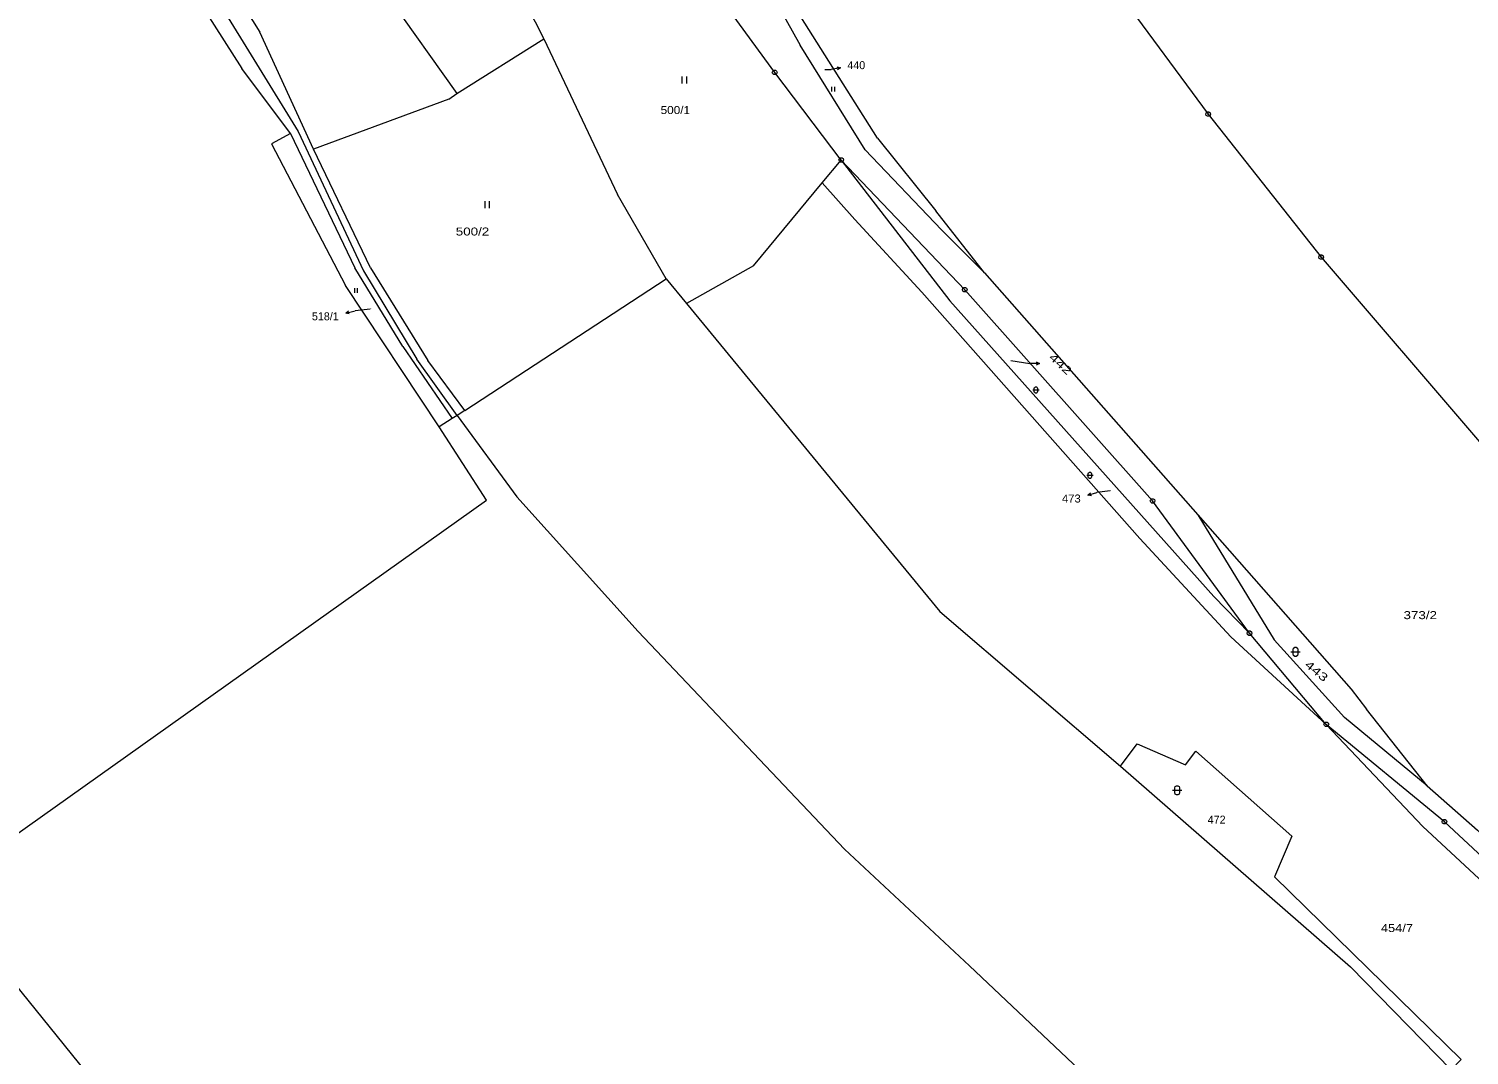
# Model space of a CAD drawing. Extents: x -687390 to -684106, y -954833 to -951648.
# Drawn here: x -686675.9 to -686369.8, y -953282.2 to -953064 of the extents above; entities that cross this region are included whole.
import ezdxf
from ezdxf.enums import TextEntityAlignment as Align

# ---------------------------------------------------------------- set-up
doc = ezdxf.new("R2010")
doc.units = 0
doc.header["$LTSCALE"] = 0.68
for name, color, linetype, lineweight in [('1', 7, 'Continuous', 13), ('3', 7, 'Continuous', 13), ('7', 7, 'Continuous', 13), ('8', 7, 'Continuous', 13)]:
    doc.layers.add(name, color=color, linetype=linetype, lineweight=lineweight)
doc.layers.add('2', color=7, linetype='Continuous')

msp = doc.modelspace()

# ---------------------------------------------------------------- linework, layer by layer
at = {"layer": '1'}
for p, q in [((-686650.19, -952985.77), (-686584.91, -953077.81)), ((-686655.57, -953033.26), (-686630.63, -953072.46)), ((-686495.55, -953087.28), (-686514, -953058.06)), ((-686516.33, -953059.65), (-686511.96, -953067.55)), ((-686615.36, -953089.59), (-686626.76, -953064.78)), ((-686566.44, -953066.15), (-686550.8, -953099.29)), ((-686498.13, -953089.75), (-686511.96, -953067.55)), ((-686620.25, -953086.28), (-686630.63, -953072.46)), ((-686586.61, -953078.97), (-686615.36, -953089.59)), ((-686620.25, -953086.28), (-686624.28, -953088.48)), ((-686620.25, -953086.28), (-686606.61, -953114.85)), ((-686624.28, -953088.48), (-686608.59, -953118.58)), ((-686603.25, -953114.87), (-686615.36, -953089.59)), ((-686495.55, -953087.28), (-686483.12, -953102.71)), ((-686503.23, -953091.93), (-686480.19, -953121.89)), ((-686498.13, -953089.75), (-686481.92, -953106.74)), ((-686507.28, -953096.81), (-686500.39, -953104.56)), ((-686486.09, -953119.99), (-686500.39, -953104.56)), ((-686472.77, -953115.91), (-686483.12, -953102.71)), ((-686472.77, -953115.91), (-686481.92, -953106.74)), ((-686596.4, -953131.6), (-686606.61, -953114.85)), ((-686603.25, -953114.87), (-686591.1, -953134.51)), ((-686521.9, -953114.4), (-686536.12, -953122.46)), ((-686588.71, -953148.66), (-686608.59, -953118.58)), ((-686486.09, -953119.99), (-686439.79, -953172.41)), ((-686480.19, -953121.89), (-686424.04, -953184.68)), ((-686596.4, -953131.6), (-686585.9, -953146.87)), ((-686584.89, -953146.23), (-686593.43, -953134.24)), ((-686583.23, -953145.16), (-686591.1, -953134.51)), ((-686585.9, -953146.87), (-686588.71, -953148.66)), ((-686584.89, -953146.23), (-686572.2, -953163.52)), ((-686578.63, -953164.25), (-686588.71, -953148.66)), ((-686691.08, -953244.15), (-686578.63, -953164.25)), ((-686572.2, -953163.52), (-686546.41, -953192.14)), ((-686427.48, -953167.34), (-686394.86, -953204.41)), ((-686416.48, -953192.52), (-686424.04, -953184.68)), ((-686502.58, -953238.38), (-686546.41, -953192.14)), ((-686394.86, -953204.41), (-686391.66, -953208.66)), ((-686378.72, -953224.93), (-686391.66, -953208.66)), ((-686400.17, -953211.88), (-686379.66, -953233.62)), ((-686378.72, -953224.93), (-686396.31, -953210.42)), ((-686443.88, -953220.8), (-686395.02, -953263.43)), ((-686502.58, -953238.38), (-686476, -953263.2)), ((-686476, -953263.2), (-686435.25, -953301.66))]:
    msp.add_line(p, q, dxfattribs=at)
for points in [[(-686744.67, -952933.19), (-686724.45, -952954.91), (-686675.78, -953000.89), (-686652.38, -953031), (-686618.65, -953085.9), (-686604.76, -953115.49), (-686593.43, -953134.24)], [(-686498.08, -952961.98), (-686495.25, -952967.14), (-686459.74, -953032.55), (-686443.92, -953056.89), (-686425.27, -953082.18), (-686401.26, -953112.58), (-686367.6, -953151.83), (-686353.01, -953164.57)], [(-686566.44, -953066.15), (-686567.94, -953063.1), (-686613.86, -952983.34)], [(-686670.54, -953001.44), (-686649.45, -953028.64), (-686626.76, -953064.78)], [(-686252.58, -953389.33), (-686292.75, -953324.92), (-686302.57, -953310.07), (-686336.76, -953268.21), (-686375.07, -953232.58), (-686400.17, -953211.88), (-686416.48, -953192.52), (-686437.08, -953164.4), (-686477, -953119.5), (-686503.23, -953091.93), (-686517.39, -953073.32), (-686528.9, -953057.45), (-686535.29, -953045.19), (-686542.46, -953027.04)], [(-686586.61, -953078.97), (-686584.91, -953077.81), (-686566.44, -953066.15)], [(-686521.9, -953114.4), (-686507.28, -953096.81), (-686503.23, -953091.93)], [(-686583.23, -953145.16), (-686540.44, -953117.21), (-686550.8, -953099.29)], [(-686540.44, -953117.21), (-686536.12, -953122.46), (-686482.27, -953187.88)], [(-686472.77, -953115.91), (-686427.48, -953167.34), (-686411.27, -953193.95), (-686396.31, -953210.42)], [(-686583.23, -953145.16), (-686584.89, -953146.23), (-686585.9, -953146.87)], [(-686400.17, -953211.88), (-686420.48, -953193.25), (-686439.79, -953172.41)], [(-686482.27, -953187.88), (-686443.88, -953220.8), (-686440.36, -953216.04), (-686430.06, -953220.52), (-686427.89, -953217.57), (-686407.47, -953235.64), (-686411.17, -953244.26), (-686371.51, -953283.1), (-686373.62, -953285.31), (-686395.02, -953263.43)], [(-686378.72, -953224.93), (-686368.07, -953234.36), (-686335.41, -953264.98), (-686302.65, -953304.78), (-686292.4, -953318.9)], [(-686379.66, -953233.62), (-686346.95, -953264.02), (-686326.9, -953287)], [(-686694.31, -953248.02), (-686654.73, -953296.99), (-686579.98, -953373.97), (-686534.21, -953420.02), (-686500.91, -953457.57), (-686468.1, -953494.74)]]:
    msp.add_lwpolyline(points, dxfattribs=at)
at = {"layer": '3'}
for p, q in [((-686537.09, -953074.15), (-686537.09, -953075.65)), ((-686536.09, -953075.65), (-686536.09, -953074.15)), ((-686505.285, -953076.395), (-686505.285, -953077.4)), ((-686504.615, -953077.4), (-686504.615, -953076.395)), ((-686579.01, -953100.68), (-686579.01, -953102.18)), ((-686578.01, -953102.18), (-686578.01, -953100.68)), ((-686606.675, -953119.145), (-686606.675, -953120.15)), ((-686606.005, -953120.15), (-686606.005, -953119.145))]:
    msp.add_line(p, q, dxfattribs=at)
for points in [[(-686462.56, -953140.81), (-686461.709, -953140.81), (-686461.22, -953140.81)], [(-686451.08, -953158.95), (-686450.229, -953158.95), (-686449.74, -953158.95)], [(-686407.71, -953196.47), (-686406.44, -953196.47), (-686405.71, -953196.47)], [(-686432.87, -953225.9), (-686431.6, -953225.9), (-686430.87, -953225.9)]]:
    msp.add_lwpolyline(points, dxfattribs=at)
for points in [[(-686462.225, -953140.475), (-686462.158, -953140.281), (-686461.99, -953140.16), (-686461.783, -953140.16), (-686461.615, -953140.281), (-686461.548, -953140.475), (-686461.548, -953141.145), (-686461.615, -953141.339), (-686461.783, -953141.46), (-686461.99, -953141.46), (-686462.158, -953141.339), (-686462.225, -953141.145)], [(-686450.745, -953158.615), (-686450.678, -953158.421), (-686450.51, -953158.3), (-686450.303, -953158.3), (-686450.135, -953158.421), (-686450.068, -953158.615), (-686450.068, -953159.285), (-686450.135, -953159.479), (-686450.303, -953159.6), (-686450.51, -953159.6), (-686450.678, -953159.479), (-686450.745, -953159.285)], [(-686407.21, -953195.97), (-686407.11, -953195.68), (-686406.86, -953195.5), (-686406.55, -953195.5), (-686406.3, -953195.68), (-686406.2, -953195.97), (-686406.2, -953196.97), (-686406.3, -953197.26), (-686406.55, -953197.44), (-686406.86, -953197.44), (-686407.11, -953197.26), (-686407.21, -953196.97)], [(-686432.37, -953225.4), (-686432.27, -953225.11), (-686432.02, -953224.93), (-686431.71, -953224.93), (-686431.46, -953225.11), (-686431.36, -953225.4), (-686431.36, -953226.4), (-686431.46, -953226.69), (-686431.71, -953226.87), (-686432.02, -953226.87), (-686432.27, -953226.69), (-686432.37, -953226.4)]]:
    msp.add_lwpolyline(points, close=True, dxfattribs=at)
at = {"layer": '7'}
for p, q in [((-686506.76, -953072.68), (-686505.42, -953072.66)), ((-686503.435, -953072.345), (-686505.42, -953072.66)), ((-686608.51, -953124.476), (-686606.56, -953123.99)), ((-686603.34, -953123.66), (-686606.56, -953123.99)), ((-686467.19, -953134.56), (-686463.16, -953135.17)), ((-686461.15, -953135.191), (-686463.16, -953135.17)), ((-686450.834, -953163.178), (-686448.9, -953162.63)), ((-686446.09, -953162.25), (-686448.9, -953162.63))]:
    msp.add_line(p, q, dxfattribs=at)
for points in [[(-686504.149, -953072.119), (-686503.435, -953072.345), (-686504.044, -953072.781)], [(-686607.779, -953124.639), (-686608.51, -953124.476), (-686607.941, -953123.989)], [(-686461.817, -953134.849), (-686461.15, -953135.191), (-686461.824, -953135.519)], [(-686450.098, -953163.318), (-686450.834, -953163.178), (-686450.281, -953162.673)]]:
    msp.add_lwpolyline(points, dxfattribs=at)
at = {"layer": '8'}
for p, q in [((-686517.51, -953073.32), (-686517.27, -953073.32)), ((-686425.39, -953082.18), (-686425.15, -953082.18)), ((-686503.35, -953091.93), (-686503.11, -953091.93)), ((-686401.38, -953112.58), (-686401.14, -953112.58)), ((-686477.12, -953119.5), (-686476.88, -953119.5)), ((-686437.2, -953164.4), (-686436.96, -953164.4)), ((-686416.6, -953192.52), (-686416.36, -953192.52)), ((-686400.29, -953211.88), (-686400.05, -953211.88)), ((-686375.19, -953232.58), (-686374.95, -953232.58))]:
    msp.add_line(p, q, dxfattribs=at)
for points in [[(-686517.24, -953072.84), (-686516.99, -953073.02), (-686516.89, -953073.31), (-686516.99, -953073.6), (-686517.24, -953073.78), (-686517.55, -953073.78), (-686517.8, -953073.6), (-686517.9, -953073.31), (-686517.8, -953073.02), (-686517.55, -953072.84)], [(-686425.12, -953081.7), (-686424.87, -953081.88), (-686424.77, -953082.17), (-686424.87, -953082.46), (-686425.12, -953082.64), (-686425.43, -953082.64), (-686425.68, -953082.46), (-686425.78, -953082.17), (-686425.68, -953081.88), (-686425.43, -953081.7)], [(-686503.08, -953091.45), (-686502.83, -953091.63), (-686502.73, -953091.92), (-686502.83, -953092.21), (-686503.08, -953092.39), (-686503.39, -953092.39), (-686503.64, -953092.21), (-686503.74, -953091.92), (-686503.64, -953091.63), (-686503.39, -953091.45)], [(-686401.11, -953112.1), (-686400.86, -953112.28), (-686400.76, -953112.57), (-686400.86, -953112.86), (-686401.11, -953113.04), (-686401.42, -953113.04), (-686401.67, -953112.86), (-686401.77, -953112.57), (-686401.67, -953112.28), (-686401.42, -953112.1)], [(-686476.85, -953119.02), (-686476.6, -953119.2), (-686476.5, -953119.49), (-686476.6, -953119.78), (-686476.85, -953119.96), (-686477.16, -953119.96), (-686477.41, -953119.78), (-686477.51, -953119.49), (-686477.41, -953119.2), (-686477.16, -953119.02)], [(-686436.93, -953163.92), (-686436.68, -953164.1), (-686436.58, -953164.39), (-686436.68, -953164.68), (-686436.93, -953164.86), (-686437.24, -953164.86), (-686437.49, -953164.68), (-686437.59, -953164.39), (-686437.49, -953164.1), (-686437.24, -953163.92)], [(-686416.33, -953192.04), (-686416.08, -953192.22), (-686415.98, -953192.51), (-686416.08, -953192.8), (-686416.33, -953192.98), (-686416.64, -953192.98), (-686416.89, -953192.8), (-686416.99, -953192.51), (-686416.89, -953192.22), (-686416.64, -953192.04)], [(-686400.02, -953211.4), (-686399.77, -953211.58), (-686399.67, -953211.87), (-686399.77, -953212.16), (-686400.02, -953212.34), (-686400.33, -953212.34), (-686400.58, -953212.16), (-686400.68, -953211.87), (-686400.58, -953211.58), (-686400.33, -953211.4)], [(-686374.92, -953232.1), (-686374.67, -953232.28), (-686374.57, -953232.57), (-686374.67, -953232.86), (-686374.92, -953233.04), (-686375.23, -953233.04), (-686375.48, -953232.86), (-686375.58, -953232.57), (-686375.48, -953232.28), (-686375.23, -953232.1)]]:
    msp.add_lwpolyline(points, close=True, dxfattribs=at)

# ---------------------------------------------------------------- texts
at = {"layer": '2'}
for s, height, p in [('440', 0.1, (-686506.732, -953072.68)), ('518/1', 0.1, (-686603.312, -953123.66)), ('472', 1.7, (-686425.375, -953232.99))]:
    msp.add_text(s, height=height, dxfattribs=at).set_placement(p)
for s, height, width, p in [('500/1', 1.7, 1.1, (-686541.625, -953082.16)), ('500/2', 1.7, 1.25, (-686585.155, -953107.98)), ('442', 0.1, 1.05, (-686467.162, -953134.56)), ('473', 0.1, 1.05, (-686446.062, -953162.25)), ('373/2', 1.7, 1.25, (-686383.765, -953189.52)), ('454/7', 1.7, 1.2, (-686388.575, -953256.03))]:
    msp.add_text(s, height=height, dxfattribs=dict(at, width=width)).set_placement(p)
at = {"layer": '2', "width": 1.45}
msp.add_text('443', height=1.7, rotation=320.226, dxfattribs=at).set_placement((-686404.905, -953199.444))
at = {"layer": '7'}
msp.add_text('440', height=1.7, dxfattribs=at).set_placement((-686501.945, -953072.62))
msp.add_text('518/1', height=1.7, dxfattribs=at).set_placement((-686610.026, -953126), align=Align.RIGHT)
at = {"layer": '7', "width": 1.45}
msp.add_text('442', height=1.7, rotation=317.82, dxfattribs=at).set_placement((-686459.26, -953134.069))
at = {"layer": '7', "width": 1.05}
msp.add_text('473', height=1.7, dxfattribs=at).set_placement((-686452.356, -953164.73), align=Align.RIGHT)

doc.saveas('drawing.dxf')
